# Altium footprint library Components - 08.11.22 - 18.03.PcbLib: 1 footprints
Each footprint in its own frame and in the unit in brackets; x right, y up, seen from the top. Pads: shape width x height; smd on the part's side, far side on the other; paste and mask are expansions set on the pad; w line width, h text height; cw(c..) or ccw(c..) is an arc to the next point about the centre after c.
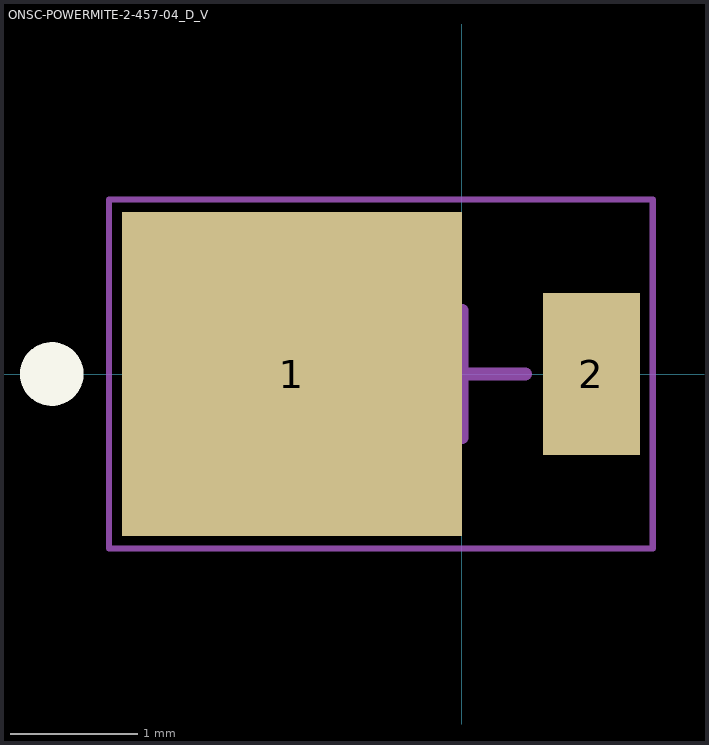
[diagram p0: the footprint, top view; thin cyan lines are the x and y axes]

## ONSC-POWERMITE-2-457-04_D_V [mil] "POWERMITE, 2-Leads, Body 1.965x1.9mm"
height 45.28
pads (2):
  rect 105.12x100 smd: 1(-52.56,0)
  rect 30x50 smd: 2(40,0)
Top Overlay:
  circle w9.84: c-126.77,0 r4.92
Mechanical 13:
  lines w3.94: -80.47,-37.4 -3.11,-37.4 -3.11,37.4 -80.47,37.4 -80.47,-37.4
Mechanical 15:
  lines w1.97: -109.06,-53.94 58.94,-53.94 58.94,53.94 -109.06,53.94 -109.06,-53.94
  lines w3.94: -19.68,0 19.68,0 ; 0,-19.68 0,19.68
3D body: height 45.28, standoff 0, extent -80.47,-37.4 -3.11,37.4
